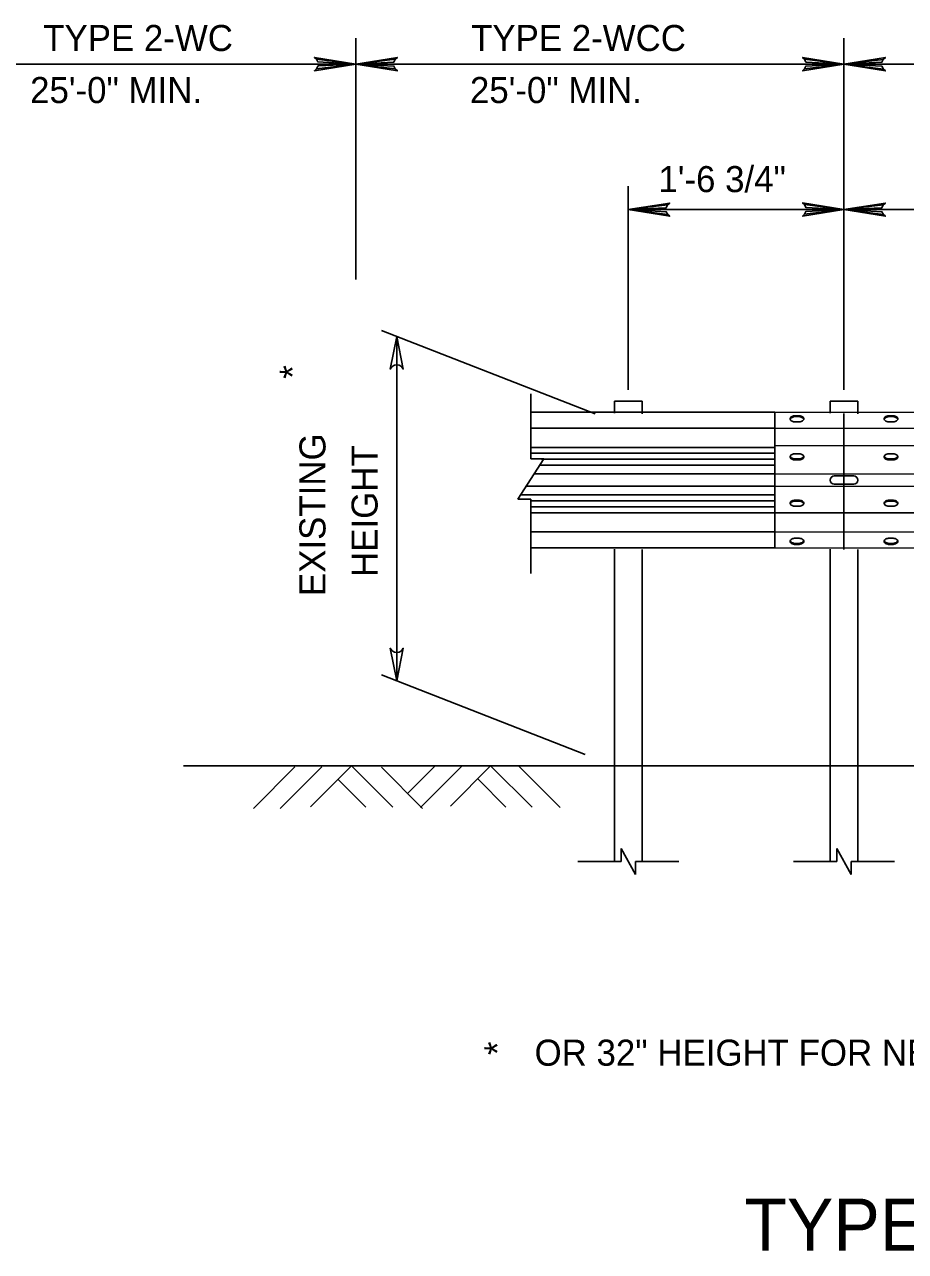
# Model space of a CAD drawing. Extents: x 637628 to 640188, y 298266 to 300751.
# Drawn here: x 639273.5 to 639374.9, y 300419.5 to 300560.7 of the extents above; entities that cross this region are included whole.
import ezdxf

# ---------------------------------------------------------------- set-up
doc = ezdxf.new("R2010")
doc.units = 0
for name, color, linetype in [('2', 7, 'Continuous'), ('S-ABUT-CONC', 7, 'Continuous'), ('S-ANNO-CELL', 7, 'Continuous'), ('S-ANNO-DIMS-MANL', 7, 'Continuous'), ('S-ANNO-T120-01', 7, 'Continuous')]:
    doc.layers.add(name, color=color, linetype=linetype)

# ---------------------------------------------------------------- blocks, each defined once
blk = doc.blocks.new('LT')
at = {"layer": 'S-ANNO-DIMS-MANL'}
blk.add_lwpolyline([(0, 0), (-0.503, 0.094), (-0.464, 0.067), (-0.444, 0.034), (-0.439, 0), (-0.444, -0.034), (-0.464, -0.067), (-0.503, -0.094)], close=True, dxfattribs=at)

msp = doc.modelspace()

# ---------------------------------------------------------------- linework, layer by layer
at = {"layer": '2'}
for p, q in [((639304.64, 300475.23), (639299.87, 300470.46)), ((639307.75, 300475.23), (639302.97, 300470.46)), ((639311.16, 300475.36), (639306.43, 300470.63)), ((639315.93, 300470.59), (639311.16, 300475.36)), ((639319.34, 300470.46), (639314.61, 300475.19)), ((639320.76, 300475.33), (639317.62, 300472.18)), ((639323.87, 300475.33), (639319.1, 300470.56)), ((639327.18, 300475.36), (639322.55, 300470.73)), ((639331.96, 300470.59), (639327.18, 300475.36)), ((639335.2, 300470.56), (639330.4, 300475.36)), ((639312.82, 300470.59), (639309.6, 300473.81)), ((639328.95, 300470.6), (639325.73, 300473.82))]:
    msp.add_line(p, q, dxfattribs=at)
for points in [[(639307.14, 300556.69), (639307.3, 300556.36), (639311.68, 300556.12), (639307.14, 300556.69), (639306.9, 300556.89), (639311.68, 300556.12), (639307.31, 300555.91), (639307.15, 300555.58), (639311.68, 300556.12), (639306.9, 300555.36), (639307.15, 300555.58)], [(639316.21, 300555.56), (639316.05, 300555.89), (639311.68, 300556.12), (639316.21, 300555.56), (639316.45, 300555.36), (639311.68, 300556.12), (639316.04, 300556.34), (639316.2, 300556.67), (639311.68, 300556.12), (639316.45, 300556.89), (639316.2, 300556.67)], [(639363.32, 300556.67), (639363.49, 300556.34), (639367.86, 300556.1), (639363.32, 300556.67), (639363.09, 300556.87), (639367.86, 300556.1), (639363.49, 300555.89), (639363.33, 300555.56), (639367.86, 300556.1), (639363.09, 300555.34), (639363.33, 300555.56)], [(639372.4, 300555.53), (639372.23, 300555.86), (639367.86, 300556.1), (639372.4, 300555.53), (639372.63, 300555.33), (639367.86, 300556.1), (639372.23, 300556.32), (639372.39, 300556.65), (639367.86, 300556.1), (639372.63, 300556.86), (639372.39, 300556.65)], [(639372.4, 300555.53), (639372.23, 300555.86), (639367.86, 300556.1), (639372.4, 300555.53), (639372.63, 300555.33), (639367.86, 300556.1), (639372.23, 300556.32), (639372.39, 300556.65), (639367.86, 300556.1), (639372.63, 300556.86), (639372.39, 300556.65)], [(639347.57, 300538.8), (639347.4, 300539.13), (639343.03, 300539.37), (639347.57, 300538.8), (639347.8, 300538.6), (639343.03, 300539.37), (639347.4, 300539.59), (639347.56, 300539.91), (639343.03, 300539.37), (639347.8, 300540.13), (639347.56, 300539.91)], [(639363.32, 300539.94), (639363.49, 300539.61), (639367.86, 300539.37), (639363.32, 300539.94), (639363.09, 300540.14), (639367.86, 300539.37), (639363.49, 300539.16), (639363.33, 300538.83), (639367.86, 300539.37), (639363.09, 300538.61), (639363.33, 300538.83)], [(639372.4, 300538.8), (639372.23, 300539.13), (639367.86, 300539.37), (639372.4, 300538.8), (639372.63, 300538.6), (639367.86, 300539.37), (639372.23, 300539.59), (639372.39, 300539.91), (639367.86, 300539.37), (639372.63, 300540.13), (639372.39, 300539.91)]]:
    msp.add_lwpolyline(points, dxfattribs=at)
at = {"layer": 'S-ABUT-CONC'}
for p, q in [((639311.68, 300531.31), (639311.68, 300559.09)), ((639367.86, 300518.62), (639367.86, 300559.09)), ((639267.9, 300556.12), (639311.68, 300556.12)), ((639311.68, 300556.1), (639367.86, 300556.1)), ((639367.86, 300556.1), (639562.85, 300556.1)), ((639343.03, 300518.62), (639343.03, 300542.08)), ((639343.03, 300539.37), (639367.86, 300539.37)), ((639367.86, 300539.37), (639465.36, 300539.37)), ((639339.23, 300515.85), (639314.61, 300525.46)), ((639316.38, 300485.14), (639316.38, 300524.77)), ((639338.05, 300476.67), (639314.61, 300485.83))]:
    msp.add_line(p, q, dxfattribs=at)
at = {"layer": 'S-ANNO-CELL'}
for p, q in [((639331.81, 300510.67), (639331.81, 300518.17)), ((639344.62, 300517.34), (639341.44, 300517.34)), ((639341.44, 300515.94), (639341.44, 300517.34)), ((639344.62, 300515.88), (639344.62, 300517.34)), ((639369.45, 300517.34), (639366.27, 300517.34)), ((639366.27, 300515.94), (639366.27, 300517.34)), ((639369.45, 300515.88), (639369.45, 300517.34)), ((639359.91, 300516.06), (639331.81, 300516.06)), ((639359.91, 300516.06), (639359.91, 300500.43)), ((639555.11, 300515.82), (639359.91, 300516.06)), ((639362.29, 300515.65), (639362.61, 300515.65)), ((639362.29, 300515.54), (639362.29, 300515.65)), ((639362.61, 300515.54), (639362.29, 300515.54)), ((639362.61, 300515.54), (639362.61, 300515.65)), ((639367.86, 300500.27), (639367.86, 300515.91)), ((639373.11, 300515.65), (639373.43, 300515.65)), ((639373.11, 300515.54), (639373.11, 300515.65)), ((639373.43, 300515.54), (639373.11, 300515.54)), ((639373.43, 300515.54), (639373.43, 300515.65)), ((639359.91, 300514.22), (639331.81, 300514.22)), ((639555.11, 300513.81), (639359.91, 300514.22)), ((639362.29, 300514.94), (639362.61, 300514.94)), ((639373.11, 300514.94), (639373.43, 300514.94)), ((639359.91, 300512), (639331.81, 300512)), ((639359.91, 300511.32), (639331.81, 300511.32)), ((639555.11, 300511.6), (639359.91, 300512.24)), ((639362.29, 300511.27), (639362.61, 300511.27)), ((639373.11, 300511.27), (639373.43, 300511.27)), ((639333.31, 300510.67), (639330.31, 300506.04)), ((639331.81, 300510.67), (639333.31, 300510.67)), ((639359.91, 300509.94), (639332.84, 300509.94)), ((639359.91, 300510.63), (639333.05, 300510.63)), ((639362.29, 300510.67), (639362.29, 300510.56)), ((639362.61, 300510.67), (639362.29, 300510.67)), ((639362.29, 300510.56), (639362.61, 300510.56)), ((639362.61, 300510.67), (639362.61, 300510.56)), ((639373.11, 300510.67), (639373.11, 300510.56)), ((639373.43, 300510.67), (639373.11, 300510.67)), ((639373.11, 300510.56), (639373.43, 300510.56)), ((639373.43, 300510.67), (639373.43, 300510.56)), ((639359.91, 300508.95), (639332.19, 300508.95)), ((639555.11, 300508.55), (639359.91, 300508.95)), ((639368.98, 300508.72), (639366.75, 300508.72)), ((639359.91, 300507.54), (639331.29, 300507.54)), ((639555.11, 300507.14), (639359.91, 300507.54)), ((639366.75, 300507.77), (639368.98, 300507.77)), ((639331.81, 300506.04), (639330.31, 300506.04)), ((639359.91, 300506.55), (639330.64, 300506.55)), ((639331.81, 300497.5), (639331.81, 300506.04)), ((639359.91, 300505.86), (639331.81, 300505.86)), ((639362.29, 300505.93), (639362.61, 300505.93)), ((639362.29, 300505.82), (639362.29, 300505.93)), ((639362.61, 300505.82), (639362.29, 300505.82)), ((639362.61, 300505.82), (639362.61, 300505.93)), ((639373.11, 300505.93), (639373.43, 300505.93)), ((639373.11, 300505.82), (639373.11, 300505.93)), ((639373.43, 300505.82), (639373.11, 300505.82)), ((639373.43, 300505.82), (639373.43, 300505.93)), ((639359.91, 300505.18), (639331.81, 300505.18)), ((639359.91, 300504.49), (639331.81, 300504.49)), ((639555.11, 300504.09), (639359.91, 300504.49)), ((639362.29, 300505.22), (639362.61, 300505.22)), ((639373.11, 300505.22), (639373.43, 300505.22)), ((639359.91, 300502.28), (639331.81, 300502.28)), ((639555.11, 300501.88), (639359.91, 300502.28)), ((639362.29, 300501.55), (639362.61, 300501.55)), ((639373.11, 300501.55), (639373.43, 300501.55)), ((639359.91, 300500.43), (639331.81, 300500.43)), ((639341.44, 300475.37), (639341.44, 300500.3)), ((639344.62, 300475.37), (639344.62, 300500.24)), ((639555.11, 300500.19), (639359.91, 300500.43)), ((639362.29, 300500.95), (639362.29, 300500.84)), ((639362.61, 300500.95), (639362.29, 300500.95)), ((639362.29, 300500.84), (639362.61, 300500.84)), ((639362.61, 300500.95), (639362.61, 300500.84)), ((639366.27, 300475.37), (639366.27, 300500.3)), ((639369.45, 300475.37), (639369.45, 300500.24)), ((639373.11, 300500.95), (639373.11, 300500.84)), ((639373.43, 300500.95), (639373.11, 300500.95)), ((639373.11, 300500.84), (639373.43, 300500.84)), ((639373.43, 300500.95), (639373.43, 300500.84)), ((639291.81, 300475.37), (639555.11, 300475.37)), ((639341.44, 300464.35), (639341.44, 300475.37)), ((639344.62, 300464.35), (639344.62, 300475.37)), ((639366.27, 300464.35), (639366.27, 300475.37)), ((639369.45, 300464.35), (639369.45, 300475.37)), ((639342.21, 300464.35), (639342.21, 300465.85)), ((639343.85, 300462.85), (639342.21, 300465.85)), ((639367.04, 300464.35), (639367.04, 300465.85)), ((639368.68, 300462.85), (639367.04, 300465.85)), ((639337.21, 300464.35), (639342.21, 300464.35)), ((639343.85, 300464.35), (639343.85, 300462.85)), ((639343.85, 300464.35), (639348.85, 300464.35)), ((639362.04, 300464.35), (639367.04, 300464.35)), ((639368.68, 300464.35), (639368.68, 300462.85)), ((639368.68, 300464.35), (639373.68, 300464.35))]:
    msp.add_line(p, q, dxfattribs=at)
for points in [[(639362.29, 300514.94), (639362.18, 300514.94), (639362.07, 300514.96), (639361.97, 300514.99), (639361.88, 300515.02), (639361.8, 300515.07), (639361.74, 300515.12), (639361.69, 300515.17), (639361.67, 300515.23), (639361.66, 300515.3), (639361.67, 300515.36), (639361.69, 300515.42), (639361.74, 300515.47), (639361.8, 300515.52), (639361.88, 300515.57), (639361.97, 300515.6), (639362.07, 300515.63), (639362.18, 300515.65), (639362.29, 300515.65)], [(639362.29, 300515.54), (639362.18, 300515.54), (639362.07, 300515.52), (639361.97, 300515.49), (639361.88, 300515.46), (639361.8, 300515.41), (639361.74, 300515.36), (639361.69, 300515.31), (639361.67, 300515.25), (639361.66, 300515.24)], [(639362.61, 300515.65), (639362.72, 300515.65), (639362.83, 300515.63), (639362.93, 300515.6), (639363.02, 300515.57), (639363.1, 300515.52), (639363.16, 300515.47), (639363.21, 300515.42), (639363.24, 300515.36), (639363.25, 300515.3), (639363.24, 300515.23), (639363.21, 300515.17), (639363.16, 300515.12), (639363.1, 300515.07), (639363.02, 300515.02), (639362.93, 300514.99), (639362.83, 300514.96), (639362.72, 300514.94), (639362.61, 300514.94)], [(639363.24, 300515.24), (639363.24, 300515.25), (639363.21, 300515.31), (639363.16, 300515.36), (639363.1, 300515.41), (639363.02, 300515.46), (639362.93, 300515.49), (639362.83, 300515.52), (639362.72, 300515.54), (639362.61, 300515.54)], [(639373.11, 300514.94), (639373, 300514.94), (639372.9, 300514.96), (639372.79, 300514.99), (639372.7, 300515.02), (639372.63, 300515.07), (639372.56, 300515.12), (639372.51, 300515.17), (639372.49, 300515.23), (639372.48, 300515.3), (639372.49, 300515.36), (639372.51, 300515.42), (639372.56, 300515.47), (639372.63, 300515.52), (639372.7, 300515.57), (639372.79, 300515.6), (639372.9, 300515.63), (639373, 300515.65), (639373.11, 300515.65)], [(639373.11, 300515.54), (639373, 300515.54), (639372.9, 300515.52), (639372.79, 300515.49), (639372.7, 300515.46), (639372.63, 300515.41), (639372.56, 300515.36), (639372.51, 300515.31), (639372.49, 300515.25), (639372.48, 300515.24)], [(639373.43, 300515.65), (639373.54, 300515.65), (639373.65, 300515.63), (639373.75, 300515.6), (639373.84, 300515.57), (639373.92, 300515.52), (639373.98, 300515.47), (639374.03, 300515.42), (639374.06, 300515.36), (639374.07, 300515.3), (639374.06, 300515.23), (639374.03, 300515.17), (639373.98, 300515.12), (639373.92, 300515.07), (639373.84, 300515.02), (639373.75, 300514.99), (639373.65, 300514.96), (639373.54, 300514.94), (639373.43, 300514.94)], [(639374.06, 300515.24), (639374.06, 300515.25), (639374.03, 300515.31), (639373.98, 300515.36), (639373.92, 300515.41), (639373.84, 300515.46), (639373.75, 300515.49), (639373.65, 300515.52), (639373.54, 300515.54), (639373.43, 300515.54)], [(639362.29, 300511.27), (639362.18, 300511.27), (639362.07, 300511.25), (639361.97, 300511.23), (639361.88, 300511.19), (639361.8, 300511.15), (639361.74, 300511.1), (639361.69, 300511.04), (639361.67, 300510.98), (639361.66, 300510.92), (639361.67, 300510.86), (639361.69, 300510.8), (639361.74, 300510.74), (639361.8, 300510.69), (639361.88, 300510.64), (639361.97, 300510.61), (639362.07, 300510.58), (639362.18, 300510.57), (639362.29, 300510.56)], [(639362.61, 300510.56), (639362.72, 300510.57), (639362.83, 300510.58), (639362.93, 300510.61), (639363.02, 300510.64), (639363.1, 300510.69), (639363.16, 300510.74), (639363.21, 300510.8), (639363.24, 300510.86), (639363.25, 300510.92), (639363.24, 300510.98), (639363.21, 300511.04), (639363.16, 300511.1), (639363.1, 300511.15), (639363.02, 300511.19), (639362.93, 300511.23), (639362.83, 300511.25), (639362.72, 300511.27), (639362.61, 300511.27)], [(639373.11, 300511.27), (639373, 300511.27), (639372.9, 300511.25), (639372.79, 300511.23), (639372.7, 300511.19), (639372.63, 300511.15), (639372.56, 300511.1), (639372.51, 300511.04), (639372.49, 300510.98), (639372.48, 300510.92), (639372.49, 300510.86), (639372.51, 300510.8), (639372.56, 300510.74), (639372.63, 300510.69), (639372.7, 300510.64), (639372.79, 300510.61), (639372.9, 300510.58), (639373, 300510.57), (639373.11, 300510.56)], [(639373.43, 300510.56), (639373.54, 300510.57), (639373.65, 300510.58), (639373.75, 300510.61), (639373.84, 300510.64), (639373.92, 300510.69), (639373.98, 300510.74), (639374.03, 300510.8), (639374.06, 300510.86), (639374.07, 300510.92), (639374.06, 300510.98), (639374.03, 300511.04), (639373.98, 300511.1), (639373.92, 300511.15), (639373.84, 300511.19), (639373.75, 300511.23), (639373.65, 300511.25), (639373.54, 300511.27), (639373.43, 300511.27)], [(639362.29, 300510.67), (639362.18, 300510.68), (639362.07, 300510.69), (639361.97, 300510.72), (639361.88, 300510.76), (639361.8, 300510.8), (639361.74, 300510.85), (639361.69, 300510.91), (639361.67, 300510.97), (639361.66, 300510.97)], [(639363.24, 300510.97), (639363.24, 300510.97), (639363.21, 300510.91), (639363.16, 300510.85), (639363.1, 300510.8), (639363.02, 300510.76), (639362.93, 300510.72), (639362.83, 300510.69), (639362.72, 300510.68), (639362.61, 300510.67)], [(639373.11, 300510.67), (639373, 300510.68), (639372.9, 300510.69), (639372.79, 300510.72), (639372.7, 300510.76), (639372.63, 300510.8), (639372.56, 300510.85), (639372.51, 300510.91), (639372.49, 300510.97), (639372.48, 300510.97)], [(639374.06, 300510.97), (639374.06, 300510.97), (639374.03, 300510.91), (639373.98, 300510.85), (639373.92, 300510.8), (639373.84, 300510.76), (639373.75, 300510.72), (639373.65, 300510.69), (639373.54, 300510.68), (639373.43, 300510.67)], [(639362.29, 300505.22), (639362.18, 300505.22), (639362.07, 300505.24), (639361.97, 300505.26), (639361.88, 300505.3), (639361.8, 300505.34), (639361.74, 300505.39), (639361.69, 300505.45), (639361.67, 300505.51), (639361.66, 300505.57), (639361.67, 300505.63), (639361.69, 300505.69), (639361.74, 300505.75), (639361.8, 300505.8), (639361.88, 300505.85), (639361.97, 300505.88), (639362.07, 300505.91), (639362.18, 300505.92), (639362.29, 300505.93)], [(639362.29, 300505.82), (639362.18, 300505.81), (639362.07, 300505.8), (639361.97, 300505.77), (639361.88, 300505.73), (639361.8, 300505.69), (639361.74, 300505.64), (639361.69, 300505.58), (639361.67, 300505.52), (639361.66, 300505.52)], [(639362.61, 300505.93), (639362.72, 300505.92), (639362.83, 300505.91), (639362.93, 300505.88), (639363.02, 300505.85), (639363.1, 300505.8), (639363.16, 300505.75), (639363.21, 300505.69), (639363.24, 300505.63), (639363.25, 300505.57), (639363.24, 300505.51), (639363.21, 300505.45), (639363.16, 300505.39), (639363.1, 300505.34), (639363.02, 300505.3), (639362.93, 300505.26), (639362.83, 300505.24), (639362.72, 300505.22), (639362.61, 300505.22)], [(639363.24, 300505.52), (639363.24, 300505.52), (639363.21, 300505.58), (639363.16, 300505.64), (639363.1, 300505.69), (639363.02, 300505.73), (639362.93, 300505.77), (639362.83, 300505.8), (639362.72, 300505.81), (639362.61, 300505.82)], [(639373.11, 300505.22), (639373, 300505.22), (639372.9, 300505.24), (639372.79, 300505.26), (639372.7, 300505.3), (639372.63, 300505.34), (639372.56, 300505.39), (639372.51, 300505.45), (639372.49, 300505.51), (639372.48, 300505.57), (639372.49, 300505.63), (639372.51, 300505.69), (639372.56, 300505.75), (639372.63, 300505.8), (639372.7, 300505.85), (639372.79, 300505.88), (639372.9, 300505.91), (639373, 300505.92), (639373.11, 300505.93)], [(639373.11, 300505.82), (639373, 300505.81), (639372.9, 300505.8), (639372.79, 300505.77), (639372.7, 300505.73), (639372.63, 300505.69), (639372.56, 300505.64), (639372.51, 300505.58), (639372.49, 300505.52), (639372.48, 300505.52)], [(639373.43, 300505.93), (639373.54, 300505.92), (639373.65, 300505.91), (639373.75, 300505.88), (639373.84, 300505.85), (639373.92, 300505.8), (639373.98, 300505.75), (639374.03, 300505.69), (639374.06, 300505.63), (639374.07, 300505.57), (639374.06, 300505.51), (639374.03, 300505.45), (639373.98, 300505.39), (639373.92, 300505.34), (639373.84, 300505.3), (639373.75, 300505.26), (639373.65, 300505.24), (639373.54, 300505.22), (639373.43, 300505.22)], [(639374.06, 300505.52), (639374.06, 300505.52), (639374.03, 300505.58), (639373.98, 300505.64), (639373.92, 300505.69), (639373.84, 300505.73), (639373.75, 300505.77), (639373.65, 300505.8), (639373.54, 300505.81), (639373.43, 300505.82)], [(639362.29, 300501.55), (639362.18, 300501.55), (639362.07, 300501.53), (639361.97, 300501.5), (639361.88, 300501.47), (639361.8, 300501.42), (639361.74, 300501.37), (639361.69, 300501.32), (639361.67, 300501.26), (639361.66, 300501.19), (639361.67, 300501.13), (639361.69, 300501.07), (639361.74, 300501.02), (639361.8, 300500.97), (639361.88, 300500.92), (639361.97, 300500.89), (639362.07, 300500.86), (639362.18, 300500.84), (639362.29, 300500.84)], [(639362.29, 300500.95), (639362.18, 300500.95), (639362.07, 300500.97), (639361.97, 300501), (639361.88, 300501.03), (639361.8, 300501.08), (639361.74, 300501.13), (639361.69, 300501.18), (639361.67, 300501.24), (639361.66, 300501.25)], [(639362.61, 300500.84), (639362.72, 300500.84), (639362.83, 300500.86), (639362.93, 300500.89), (639363.02, 300500.92), (639363.1, 300500.97), (639363.16, 300501.02), (639363.21, 300501.07), (639363.24, 300501.13), (639363.25, 300501.19), (639363.24, 300501.26), (639363.21, 300501.32), (639363.16, 300501.37), (639363.1, 300501.42), (639363.02, 300501.47), (639362.93, 300501.5), (639362.83, 300501.53), (639362.72, 300501.55), (639362.61, 300501.55)], [(639363.24, 300501.25), (639363.24, 300501.24), (639363.21, 300501.18), (639363.16, 300501.13), (639363.1, 300501.08), (639363.02, 300501.03), (639362.93, 300501), (639362.83, 300500.97), (639362.72, 300500.95), (639362.61, 300500.95)], [(639373.11, 300501.55), (639373, 300501.55), (639372.9, 300501.53), (639372.79, 300501.5), (639372.7, 300501.47), (639372.63, 300501.42), (639372.56, 300501.37), (639372.51, 300501.32), (639372.49, 300501.26), (639372.48, 300501.19), (639372.49, 300501.13), (639372.51, 300501.07), (639372.56, 300501.02), (639372.63, 300500.97), (639372.7, 300500.92), (639372.79, 300500.89), (639372.9, 300500.86), (639373, 300500.84), (639373.11, 300500.84)], [(639373.11, 300500.95), (639373, 300500.95), (639372.9, 300500.97), (639372.79, 300501), (639372.7, 300501.03), (639372.63, 300501.08), (639372.56, 300501.13), (639372.51, 300501.18), (639372.49, 300501.24), (639372.48, 300501.25)], [(639373.43, 300500.84), (639373.54, 300500.84), (639373.65, 300500.86), (639373.75, 300500.89), (639373.84, 300500.92), (639373.92, 300500.97), (639373.98, 300501.02), (639374.03, 300501.07), (639374.06, 300501.13), (639374.07, 300501.19), (639374.06, 300501.26), (639374.03, 300501.32), (639373.98, 300501.37), (639373.92, 300501.42), (639373.84, 300501.47), (639373.75, 300501.5), (639373.65, 300501.53), (639373.54, 300501.55), (639373.43, 300501.55)], [(639374.06, 300501.25), (639374.06, 300501.24), (639374.03, 300501.18), (639373.98, 300501.13), (639373.92, 300501.08), (639373.84, 300501.03), (639373.75, 300501), (639373.65, 300500.97), (639373.54, 300500.95), (639373.43, 300500.95)]]:
    msp.add_lwpolyline(points, dxfattribs=at)
for centre, start, end in [((639366.75, 300508.24), 90, 270), ((639368.98, 300508.24), 270, 90)]:
    msp.add_arc(centre, 0.477, start, end, dxfattribs=at)

# ---------------------------------------------------------------- block references
at = {"layer": 'S-ABUT-CONC'}
for p, xscale, yscale, rotation in [((639316.38, 300524.77), 7.4533753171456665, -7.9469763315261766, 90.00000000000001), ((639316.38, 300485.14), 7.453375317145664, 7.946976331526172, -90)]:
    msp.add_blockref('LT', p, dxfattribs=dict(at, xscale=xscale, yscale=yscale, rotation=rotation))

# ---------------------------------------------------------------- texts
for s, p in [('TYPE 2-WC', (639275.67, 300557.62)), ('TYPE 2-WCC', (639324.93, 300557.62)), ('25\'-0" MIN.', (639274.16, 300551.63)), ('25\'-0" MIN.', (639324.8, 300551.63)), ('1\'-6 3/4"', (639346.5, 300541.38)), ('OR 32" HEIGHT FOR NEW CONSTRUCTION', (639332.24, 300440.84))]:
    msp.add_text(s, height=3, dxfattribs=at).set_placement(p)
for s, p in [('*', (639305.89, 300519.9)), ('EXISTING', (639308.17, 300494.89)), ('HEIGHT', (639314.17, 300497.09)), ('*', (639329.47, 300442.06))]:
    msp.add_text(s, height=3, rotation=90, dxfattribs=at).set_placement(p)
at = {"layer": 'S-ANNO-T120-01'}
msp.add_text('TYPE 2-WCC GUIDE RAIL HEIGHT TRANSITION TO TYPE 31-S GUIDE RAIL', height=6, dxfattribs=at).set_placement((639356.39, 300419.55))

doc.saveas('drawing.dxf')
